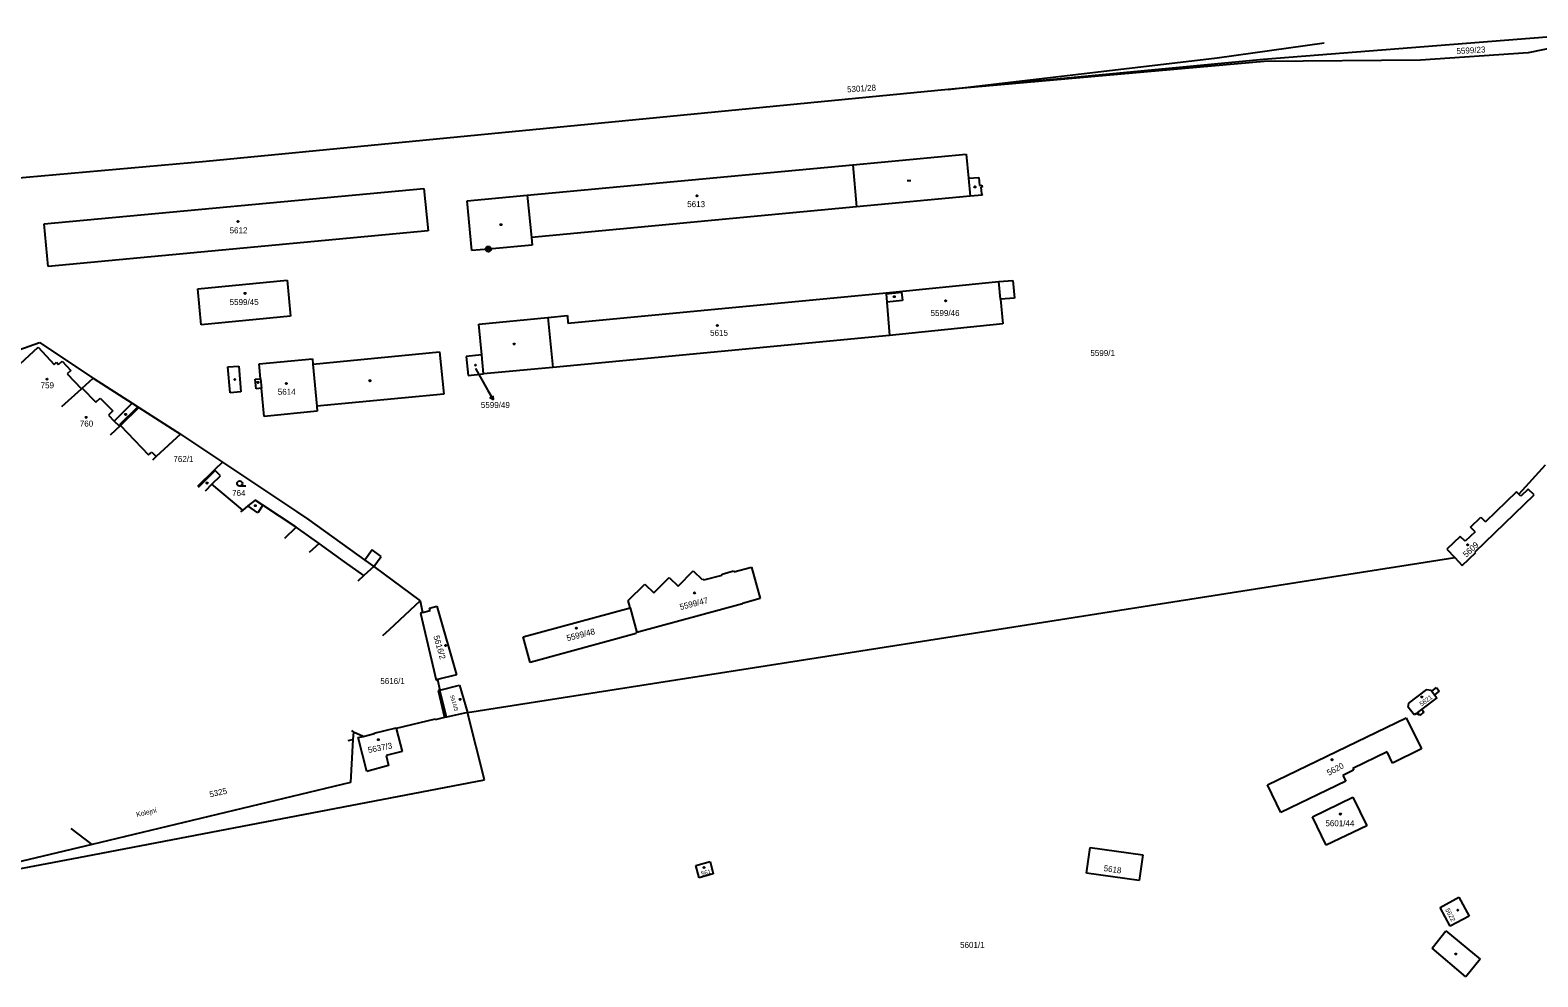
# Model space of a CAD drawing. Extents: x -825057 to -819383, y -1071633 to -1067888.
# Drawn here: x -821360.1 to -820932.9, y -1070125.7 to -1069857.7 of the extents above; entities that cross this region are included whole.
import ezdxf

# ---------------------------------------------------------------- set-up
doc = ezdxf.new("R2010")
doc.units = 0
for name, color, linetype in [('Vrstva 1', 7, 'Continuous'), ('Vrstva 15', 7, 'Continuous'), ('Vrstva 16', 7, 'Continuous'), ('Vrstva 18', 7, 'Continuous'), ('Vrstva 19', 7, 'Continuous'), ('Vrstva 24', 7, 'Continuous'), ('Vrstva 25', 7, 'Continuous'), ('Vrstva 4', 7, 'Continuous')]:
    doc.layers.add(name, color=color, linetype=linetype)

msp = doc.modelspace()

# ---------------------------------------------------------------- linework, layer by layer
at = {"layer": 'Vrstva 1'}
for p, q in [((-820904.63, -1069857.69), (-821010.61, -1069866.01)), ((-820904.63, -1069857.69), (-820935.6, -1069864.1)), ((-820935.6, -1069864.1), (-820966.1, -1069866.2)), ((-821010.61, -1069866.01), (-821099.96, -1069874.51)), ((-821010.4, -1069866.6), (-821099.96, -1069874.51)), ((-820966.1, -1069866.2), (-821010.4, -1069866.6)), ((-821099.96, -1069874.51), (-821204.97, -1069884.66)), ((-821204.97, -1069884.66), (-821310.18, -1069894.83)), ((-821310.18, -1069894.83), (-821394.16, -1069902.36)), ((-821126.99, -1069895.8), (-821094.83, -1069892.79)), ((-821094.83, -1069892.79), (-821094.2, -1069899.61)), ((-821219.2, -1069904.42), (-821126.99, -1069895.8)), ((-821356.08, -1069912.51), (-821248.48, -1069902.48)), ((-821248.48, -1069902.48), (-821247.33, -1069914.47)), ((-821094.2, -1069899.61), (-821091.31, -1069899.42)), ((-821091.31, -1069899.42), (-821091.08, -1069901.64)), ((-821091.08, -1069901.64), (-821090.41, -1069901.57)), ((-821090.35, -1069902.14), (-821090.74, -1069902.17)), ((-821090.74, -1069902.17), (-821090.55, -1069904.06)), ((-821090.41, -1069901.57), (-821090.35, -1069902.14)), ((-821236.23, -1069906.01), (-821219.2, -1069904.42)), ((-821234.89, -1069920.11), (-821236.23, -1069906.01)), ((-821093.74, -1069904.69), (-821125.89, -1069907.73)), ((-821090.36, -1069904.37), (-821093.74, -1069904.69)), ((-821090.55, -1069904.06), (-821090.4, -1069904.04)), ((-821090.4, -1069904.04), (-821090.36, -1069904.37)), ((-821125.89, -1069907.73), (-821218, -1069916.36)), ((-821354.95, -1069924.62), (-821356.08, -1069912.51)), ((-821247.33, -1069914.47), (-821354.95, -1069924.62)), ((-821230.23, -1069919.68), (-821234.89, -1069920.11)), ((-821217.78, -1069918.52), (-821230.23, -1069919.68)), ((-821218, -1069916.36), (-821217.78, -1069918.52)), ((-821312.51, -1069930.89), (-821287.26, -1069928.49)), ((-821287.26, -1069928.49), (-821286.29, -1069938.67)), ((-821117.54, -1069932.09), (-821085.6, -1069928.83)), ((-821085.6, -1069928.83), (-821081.67, -1069928.55)), ((-821081.67, -1069928.55), (-821081.2, -1069933.55)), ((-821311.6, -1069941.12), (-821312.51, -1069930.89)), ((-821207.69, -1069940.62), (-821117.54, -1069932.09)), ((-821117.54, -1069932.09), (-821117.52, -1069932.34)), ((-821117.52, -1069932.34), (-821113.16, -1069931.9)), ((-821113.16, -1069931.9), (-821112.89, -1069934.23)), ((-821112.89, -1069934.23), (-821117.33, -1069934.69)), ((-821117.33, -1069934.69), (-821116.55, -1069944.11)), ((-821081.2, -1069933.55), (-821085.16, -1069933.89)), ((-821085.16, -1069933.89), (-821084.45, -1069940.8)), ((-821286.29, -1069938.67), (-821311.6, -1069941.12)), ((-821232.95, -1069940.9), (-821213.34, -1069939.04)), ((-821232.12, -1069949.62), (-821232.95, -1069940.9)), ((-821213.34, -1069939.04), (-821207.85, -1069938.52)), ((-821207.85, -1069938.52), (-821207.69, -1069940.62)), ((-821084.45, -1069940.8), (-821116.55, -1069944.11)), ((-821116.55, -1069944.11), (-821212.01, -1069953.18)), ((-821369.19, -1069950.3), (-821357.45, -1069946.12)), ((-821357.45, -1069946.12), (-821342.21, -1069956.25)), ((-821279.92, -1069952.26), (-821244.07, -1069948.76)), ((-821244.07, -1069948.76), (-821242.89, -1069960.8)), ((-821232.12, -1069949.62), (-821236.51, -1069950.05)), ((-821236.51, -1069950.05), (-821235.98, -1069955.47)), ((-821231.61, -1069955.04), (-821232.12, -1069949.62)), ((-821295.15, -1069952.17), (-821280.05, -1069950.77)), ((-821294.76, -1069956.41), (-821295.15, -1069952.17)), ((-821280.05, -1069950.77), (-821279.92, -1069952.26)), ((-821212.01, -1069953.18), (-821231.61, -1069955.04)), ((-821345.34, -1069959.01), (-821342.21, -1069956.25)), ((-821342.21, -1069956.25), (-821331.11, -1069963.33)), ((-821296.28, -1069956.55), (-821294.76, -1069956.41)), ((-821296.04, -1069959.2), (-821296.28, -1069956.55)), ((-821235.98, -1069955.47), (-821231.61, -1069955.04)), ((-821351.12, -1069964.25), (-821345.55, -1069959.22)), ((-821345.55, -1069959.22), (-821345.34, -1069959.01)), ((-821294.51, -1069959.06), (-821296.04, -1069959.2)), ((-821293.77, -1069967.07), (-821294.51, -1069959.06)), ((-821242.89, -1069960.8), (-821278.84, -1069964.11)), ((-821329.25, -1069964.52), (-821334.5, -1069969.62)), ((-821331.11, -1069963.33), (-821329.56, -1069964.32)), ((-821329.56, -1069964.32), (-821329.25, -1069964.52)), ((-821329.25, -1069964.52), (-821317.44, -1069972.1)), ((-821278.7, -1069965.6), (-821293.77, -1069967.07)), ((-821278.84, -1069964.11), (-821278.7, -1069965.6)), ((-821334.5, -1069969.62), (-821337.41, -1069972.32)), ((-821317.44, -1069972.1), (-821324.37, -1069978.44)), ((-821317.44, -1069972.1), (-821305.58, -1069979.99)), ((-821324.37, -1069978.44), (-821325.41, -1069979.4)), ((-821305.58, -1069979.99), (-821307.81, -1069982.16)), ((-821305.58, -1069979.99), (-821296.49, -1069986.04)), ((-821307.81, -1069982.16), (-821312.67, -1069986.91)), ((-821308.56, -1069986.27), (-821306.12, -1069983.89)), ((-821307.59, -1069982.38), (-821307.81, -1069982.16)), ((-821306.12, -1069983.89), (-821307.59, -1069982.38)), ((-820930.78, -1069980.82), (-820938.28, -1069989.09)), ((-821299.82, -1069993.57), (-821308.56, -1069986.27)), ((-821296.49, -1069986.04), (-821284.57, -1069993.97)), ((-820938.97, -1069988.37), (-820947.77, -1069996.88)), ((-820938.28, -1069989.09), (-820938.97, -1069988.37)), ((-820935.6, -1069987.62), (-820937.72, -1069989.67)), ((-820933.96, -1069989.25), (-820935.6, -1069987.62)), ((-821298.38, -1069992.35), (-821299.82, -1069993.57)), ((-821296.31, -1069990.73), (-821298.38, -1069992.35)), ((-821294.15, -1069992.15), (-821296.31, -1069990.73)), ((-821284.66, -1069998.4), (-821294.15, -1069992.15)), ((-820950.64, -1070005.41), (-820933.96, -1069989.25)), ((-820937.72, -1069989.67), (-820938.28, -1069989.09)), ((-821299.82, -1069993.57), (-821300.46, -1069994.1)), ((-821284.57, -1069993.97), (-821281.1, -1069996.38)), ((-821281.1, -1069996.38), (-821265.24, -1070007.72)), ((-820951.97, -1069998.38), (-820949.05, -1069995.55)), ((-820949.05, -1069995.55), (-820947.77, -1069996.88)), ((-821278.16, -1070003.04), (-821284.66, -1069998.4)), ((-820954.86, -1070001.01), (-820958.67, -1070004.65)), ((-820953.52, -1070002.4), (-820954.86, -1070001.01)), ((-820950.68, -1069999.7), (-820953.52, -1070002.4)), ((-820950.68, -1069999.7), (-820951.97, -1069998.38)), ((-821278.16, -1070003.04), (-821280.97, -1070005.59)), ((-821271.03, -1070008.2), (-821278.16, -1070003.04)), ((-820958.67, -1070004.65), (-820956.42, -1070007.02)), ((-820954.31, -1070009.24), (-820950.48, -1070005.58)), ((-820950.48, -1070005.58), (-820950.64, -1070005.41)), ((-821265.53, -1070012.14), (-821271.03, -1070008.2)), ((-821262.68, -1070009.55), (-821265.53, -1070012.14)), ((-821265.24, -1070007.72), (-821262.68, -1070009.55)), ((-821262.68, -1070009.55), (-821249.59, -1070019.24)), ((-821160.73, -1070011.1), (-821155.64, -1070009.76)), ((-821155.64, -1070009.76), (-821153.2, -1070018.65)), ((-821087.99, -1070027.64), (-820956.42, -1070007.02)), ((-820956.42, -1070007.02), (-820954.31, -1070009.24)), ((-821265.53, -1070012.14), (-821267.22, -1070013.69)), ((-821183.33, -1070017.02), (-821179.04, -1070012.7)), ((-821179.04, -1070012.7), (-821176.47, -1070015.16)), ((-821176.47, -1070015.16), (-821172.19, -1070010.81)), ((-821172.19, -1070010.81), (-821169.68, -1070013.24)), ((-821169.68, -1070013.24), (-821169.45, -1070013.08)), ((-821169.45, -1070013.08), (-821169.15, -1070013.35)), ((-821169.15, -1070013.35), (-821163.97, -1070011.96)), ((-821164.01, -1070011.69), (-821160.8, -1070010.82)), ((-821163.97, -1070011.96), (-821164.01, -1070011.69)), ((-821160.8, -1070010.82), (-821160.73, -1070011.1)), ((-821190.61, -1070019.17), (-821185.89, -1070014.53)), ((-821185.89, -1070014.53), (-821183.33, -1070017.02)), ((-821153.2, -1070018.65), (-821158.27, -1070020.02)), ((-821249.59, -1070019.24), (-821258.36, -1070027.44)), ((-821249.59, -1070019.24), (-821248.91, -1070022.58)), ((-821248.91, -1070022.58), (-821249.48, -1070022.73)), ((-821249.48, -1070022.73), (-821245.07, -1070041.7)), ((-821248.91, -1070022.58), (-821246.7, -1070021.98)), ((-821246.88, -1070021.31), (-821244.87, -1070020.75)), ((-821246.7, -1070021.98), (-821246.88, -1070021.31)), ((-821244.87, -1070020.75), (-821244.68, -1070021.43)), ((-821244.68, -1070021.43), (-821239.23, -1070040.23)), ((-821220.34, -1070029.47), (-821190.09, -1070021.23)), ((-821190.09, -1070021.23), (-821190.61, -1070019.17)), ((-821190.09, -1070021.23), (-821188.13, -1070028.23)), ((-821158.23, -1070020.16), (-821188.13, -1070028.23)), ((-821158.27, -1070020.02), (-821158.23, -1070020.16)), ((-821258.36, -1070027.44), (-821260.23, -1070029.19)), ((-821236.18, -1070050.87), (-821087.99, -1070027.64)), ((-821218.37, -1070036.69), (-821220.34, -1070029.47)), ((-821188.38, -1070028.53), (-821218.37, -1070036.69)), ((-821188.13, -1070028.23), (-821188.44, -1070028.31)), ((-821188.44, -1070028.31), (-821188.38, -1070028.53)), ((-821245.07, -1070041.7), (-821244.63, -1070041.59)), ((-821239.23, -1070040.23), (-821244.63, -1070041.59)), ((-821244.63, -1070041.59), (-821243.95, -1070044.52)), ((-821243.95, -1070044.52), (-821238.41, -1070043.13)), ((-821238.41, -1070043.13), (-821236.18, -1070050.87)), ((-820962.96, -1070044.81), (-820961.6, -1070043.79)), ((-820961.6, -1070043.79), (-820960.88, -1070044.8)), ((-821243.95, -1070044.52), (-821244.41, -1070044.64)), ((-821244.41, -1070044.64), (-821242.69, -1070052.35)), ((-820969.67, -1070049.36), (-820969.48, -1070048.21)), ((-820969.48, -1070048.21), (-820964.32, -1070044.38)), ((-820961.5, -1070046.76), (-820965.8, -1070049.99)), ((-820964.32, -1070044.38), (-820963.14, -1070044.56)), ((-820963.14, -1070044.56), (-820962.96, -1070044.81)), ((-820960.88, -1070044.8), (-820962.17, -1070045.86)), ((-820962.17, -1070045.86), (-820961.5, -1070046.76)), ((-821245.31, -1070052.82), (-821256.32, -1070055.41)), ((-821245.27, -1070052.96), (-821245.31, -1070052.82)), ((-821242.69, -1070052.35), (-821245.27, -1070052.96)), ((-821242.12, -1070052.22), (-821242.69, -1070052.35)), ((-821236.18, -1070050.87), (-821242.12, -1070052.22)), ((-821231.29, -1070069.95), (-821236.18, -1070050.87)), ((-821009.46, -1070071.37), (-820970.17, -1070052.4)), ((-820970.17, -1070052.4), (-820965.84, -1070061.19)), ((-820967.91, -1070051.58), (-820969.67, -1070049.36)), ((-820967.44, -1070051.23), (-820967.91, -1070051.58)), ((-820967.25, -1070051.47), (-820967.44, -1070051.23)), ((-820966.84, -1070051.16), (-820967.25, -1070051.47)), ((-820966.42, -1070051.71), (-820966.84, -1070051.16)), ((-820965.18, -1070050.82), (-820966.42, -1070051.71)), ((-820965.8, -1070049.99), (-820965.18, -1070050.82)), ((-821269, -1070055.95), (-821268.48, -1070056.5)), ((-821268.48, -1070056.5), (-821268.6, -1070058.51)), ((-821265.69, -1070057.64), (-821268.48, -1070056.5)), ((-821265.69, -1070057.64), (-821262.54, -1070056.84)), ((-821262.57, -1070056.72), (-821256.38, -1070055.19)), ((-821262.54, -1070056.84), (-821262.57, -1070056.72)), ((-821256.38, -1070055.19), (-821256.32, -1070055.41)), ((-821256.32, -1070055.41), (-821254.68, -1070061.91)), ((-821269.94, -1070058.82), (-821268.6, -1070058.51)), ((-821268.6, -1070058.51), (-821269.3, -1070070.69)), ((-821267.13, -1070058), (-821265.69, -1070057.64)), ((-821264.67, -1070067.57), (-821267.13, -1070058)), ((-820965.84, -1070061.19), (-820974.11, -1070065.2)), ((-821254.68, -1070061.91), (-821259.17, -1070063.06)), ((-821259.17, -1070063.06), (-821258.49, -1070065.94)), ((-820975.63, -1070062.06), (-820985.32, -1070066.76)), ((-820974.11, -1070065.2), (-820975.63, -1070062.06)), ((-821344.25, -1070091.52), (-821231.29, -1070069.95)), ((-821258.49, -1070065.94), (-821264.67, -1070067.57)), ((-820985.1, -1070067.21), (-820988.11, -1070068.69)), ((-820988.11, -1070068.69), (-820987.3, -1070070.36)), ((-820985.32, -1070066.76), (-820985.1, -1070067.21)), ((-821269.3, -1070070.69), (-821342.51, -1070088.26)), ((-821005.67, -1070079.24), (-821009.46, -1070071.37)), ((-820987.3, -1070070.36), (-821005.67, -1070079.24)), ((-820996.77, -1070080.39), (-820985.3, -1070074.82)), ((-820985.3, -1070074.82), (-820981.37, -1070082.94)), ((-820992.84, -1070088.49), (-820996.77, -1070080.39)), ((-821342.51, -1070088.26), (-821348.44, -1070083.73)), ((-820981.37, -1070082.94), (-820992.84, -1070088.49)), ((-821342.51, -1070088.26), (-821364.34, -1070093.49)), ((-821060.77, -1070096.38), (-821059.71, -1070089.09)), ((-821059.71, -1070089.09), (-821044.85, -1070091.16)), ((-821044.85, -1070091.16), (-821045.87, -1070098.45)), ((-821444.24, -1070110.62), (-821344.25, -1070091.52)), ((-821171.43, -1070094.17), (-821167.43, -1070093.11)), ((-821170.51, -1070097.67), (-821171.43, -1070094.17)), ((-821167.43, -1070093.11), (-821166.5, -1070096.61)), ((-821166.5, -1070096.61), (-821170.51, -1070097.67)), ((-821045.87, -1070098.45), (-821060.77, -1070096.38)), ((-820960.53, -1070106.07), (-820955.3, -1070103.16)), ((-820955.3, -1070103.16), (-820952.4, -1070108.52)), ((-820957.7, -1070111.36), (-820960.53, -1070106.07)), ((-820952.4, -1070108.52), (-820957.7, -1070111.36))]:
    msp.add_line(p, q, dxfattribs=at)
at = {"layer": 'Vrstva 16'}
for p, q in [((-821233.88, -1069953.53), (-821230.37, -1069959.7)), ((-821230.37, -1069959.7), (-821228.885, -1069962.307))]:
    msp.add_line(p, q, dxfattribs=at)
msp.add_lwpolyline([(-821228.946, -1069961.19), (-821228.885, -1069962.307), (-821229.815, -1069961.685)], dxfattribs=at)
at = {"layer": 'Vrstva 24'}
for p, q in [((-821230.98, -1069919.68), (-821229.48, -1069919.68)), ((-821230.954, -1069919.486), (-821229.506, -1069919.874)), ((-821230.954, -1069919.874), (-821229.506, -1069919.486)), ((-821230.879, -1069919.305), (-821229.581, -1069920.055)), ((-821230.879, -1069920.055), (-821229.581, -1069919.305)), ((-821230.76, -1069920.21), (-821229.7, -1069919.15)), ((-821230.76, -1069919.15), (-821229.7, -1069920.21))]:
    msp.add_line(p, q, dxfattribs=at)
msp.add_circle((-821230.23, -1069919.68), 0.75, dxfattribs=at)
at = {"layer": 'Vrstva 25'}
for p, q in [((-821111.56, -1069900.29), (-821110.56, -1069900.29)), ((-821298.94, -1069986.81), (-821300.69, -1069986.81))]:
    msp.add_line(p, q, dxfattribs=at)
for centre, radius in [((-821092.38, -1069902.08), 0.175), ((-821171.13, -1069904.59), 0.175), ((-821301.17, -1069911.86), 0.175), ((-821226.67, -1069912.77), 0.175), ((-821299.17, -1069932.23), 0.175), ((-821115.23, -1069933.14), 0.175), ((-821100.7, -1069934.33), 0.175), ((-821165.39, -1069941.31), 0.175), ((-821222.93, -1069946.55), 0.175), ((-821233.88, -1069952.55), 0.175), ((-821355.26, -1069956.49), 0.175), ((-821302.08, -1069956.59), 0.175), ((-821295.53, -1069957.43), 0.175), ((-821287.48, -1069957.72), 0.175), ((-821263.79, -1069956.95), 0.175), ((-821344.17, -1069967.33), 0.175), ((-821333.02, -1069966.49), 0.175), ((-821309.93, -1069985.93), 0.175), ((-821300.69, -1069986.06), 0.75), ((-821296.25, -1069992.31), 0.175), ((-820952.8, -1070003.43), 0.175), ((-821171.83, -1070017.03), 0.175), ((-821205.33, -1070027.01), 0.175), ((-821242.35, -1070031.91), 0.175), ((-821238.22, -1070047.18), 0.175), ((-820965.78, -1070046.51), 0.175), ((-821261.4, -1070058.57), 0.175), ((-820991.21, -1070064.27), 0.175), ((-820988.84, -1070079.65), 0.175), ((-821169.14, -1070094.76), 0.175), ((-820955.56, -1070106.85), 0.175), ((-820956.12, -1070119.28), 0.175)]:
    msp.add_circle(centre, radius, dxfattribs=at)
at = {"layer": 'Vrstva 4'}
for p, q in [((-821023.78, -1069865.56), (-820993.46, -1069861.27)), ((-821058.25, -1069869.59), (-821023.78, -1069865.56)), ((-821099.96, -1069874.51), (-821058.25, -1069869.59)), ((-821126.99, -1069895.8), (-821125.89, -1069907.73)), ((-821094.2, -1069899.61), (-821093.74, -1069904.69)), ((-821219.2, -1069904.42), (-821218, -1069916.36)), ((-821085.16, -1069933.89), (-821085.6, -1069928.83)), ((-821117.52, -1069932.34), (-821117.33, -1069934.69)), ((-821213.34, -1069939.04), (-821212.01, -1069953.18)), ((-821365.33, -1069954.47), (-821357.83, -1069947.42)), ((-821357.83, -1069947.42), (-821353.22, -1069952.34)), ((-821353.22, -1069952.34), (-821352.55, -1069951.72)), ((-821352.55, -1069951.72), (-821351.98, -1069952.32)), ((-821351.98, -1069952.32), (-821350.99, -1069951.39)), ((-821350.99, -1069951.39), (-821348.54, -1069954.01)), ((-821348.54, -1069954.01), (-821349.56, -1069954.99)), ((-821304.03, -1069953.05), (-821300.95, -1069952.82)), ((-821303.42, -1069960.39), (-821304.03, -1069953.05)), ((-821300.95, -1069952.82), (-821300.38, -1069960.11)), ((-821279.92, -1069952.26), (-821278.84, -1069964.11)), ((-821349.56, -1069954.99), (-821345.55, -1069959.22)), ((-821294.76, -1069956.41), (-821294.51, -1069959.06)), ((-821345.34, -1069959.01), (-821341.47, -1069963.03)), ((-821341.47, -1069963.03), (-821340.25, -1069961.85)), ((-821340.25, -1069961.85), (-821338.04, -1069964.09)), ((-821300.38, -1069960.11), (-821303.42, -1069960.39)), ((-821338.04, -1069964.09), (-821336.65, -1069965.46)), ((-821336.65, -1069965.46), (-821337.85, -1069966.71)), ((-821337.85, -1069966.71), (-821336.21, -1069968.38)), ((-821336.21, -1069968.38), (-821331.11, -1069963.33)), ((-821329.56, -1069964.32), (-821334.71, -1069969.41)), ((-821336.21, -1069968.38), (-821334.96, -1069969.65)), ((-821334.96, -1069969.65), (-821334.71, -1069969.41)), ((-821334.71, -1069969.41), (-821334.5, -1069969.62)), ((-821334.5, -1069969.62), (-821326.56, -1069977.97)), ((-821326.56, -1069977.97), (-821325.57, -1069977.17)), ((-821325.57, -1069977.17), (-821324.37, -1069978.44)), ((-821312.33, -1069987.11), (-821307.59, -1069982.38)), ((-821308.56, -1069986.27), (-821310.51, -1069988.18)), ((-821295.54, -1069994.37), (-821298.38, -1069992.35)), ((-821294.15, -1069992.15), (-821295.54, -1069994.37)), ((-821287.93, -1070001.49), (-821284.66, -1069998.4)), ((-821263.13, -1070004.85), (-821265.24, -1070007.72)), ((-821260.59, -1070006.68), (-821263.13, -1070004.85)), ((-821262.68, -1070009.55), (-821260.59, -1070006.68)), ((-821242.12, -1070052.22), (-821243.95, -1070044.52)), ((-820962.96, -1070044.81), (-820962.17, -1070045.86)), ((-820967.02, -1070050.91), (-820967.44, -1070051.23)), ((-820965.8, -1070049.99), (-820967.02, -1070050.91)), ((-820962.88, -1070117.59), (-820958.97, -1070112.75)), ((-820958.97, -1070112.75), (-820949.27, -1070120.76)), ((-820953.32, -1070125.73), (-820962.88, -1070117.59)), ((-820949.27, -1070120.76), (-820953.32, -1070125.73))]:
    msp.add_line(p, q, dxfattribs=at)

# ---------------------------------------------------------------- texts
at = {"layer": 'Vrstva 15'}
msp.add_text('Kolejní', height=1.4, rotation=12.6, dxfattribs=at).set_placement((-821329.83, -1070080.481))
at = {"layer": 'Vrstva 16'}
for s, p in [('5599/49', (-821232.358, -1069964.66)), ('5601/1', (-821096.588, -1070117.54))]:
    msp.add_text(s, height=1.7, dxfattribs=at).set_placement(p)
at = {"layer": 'Vrstva 18'}
for s, rotation, p in [('5599/23', 3.6, (-820955.891, -1069864.491)), ('5301/28', 3.6, (-821128.565, -1069875.301)), ('5325', 12.6, (-821309.055, -1070074.948)), ('5618', 351.9, (-821056.003, -1070095.776))]:
    msp.add_text(s, height=1.7, rotation=rotation, dxfattribs=at).set_placement(p)
for s, p in [('5599/1', (-821059.663, -1069949.95)), ('764', (-821302.838, -1069989.58)), ('5616/1', (-821260.844, -1070042.83))]:
    msp.add_text(s, height=1.7, dxfattribs=at).set_placement(p)
at = {"layer": 'Vrstva 19'}
for s, height, p in [('5613', 1.7, (-821173.894, -1069907.8)), ('5612', 1.7, (-821303.552, -1069915.22)), ('5599/45', 1.7, (-821303.54, -1069935.52)), ('5599/46', 1.7, (-821104.958, -1069938.63)), ('5615', 1.7, (-821167.418, -1069944.24)), ('5599/49', 0.1, (-821234.082, -1069953.53)), ('759', 1.7, (-821357.09, -1069959.09)), ('5614', 1.7, (-821289.886, -1069960.94)), ('760', 1.7, (-821345.982, -1069969.93)), ('762/1', 1.7, (-821319.462, -1069979.95)), ('5601/44', 1.7, (-820993.08, -1070083.09))]:
    msp.add_text(s, height=height, dxfattribs=at).set_placement(p)
for s, height, rotation, p in [('5609', 1.7, 43.2, (-820953.17, -1070007.09)), ('5599/47', 1.7, 14.2065, (-821175.801, -1070021.893)), ('5599/48', 1.7, 14.2425, (-821207.842, -1070030.699)), ('5616/2', 1.7, 286.0929, (-821245.832, -1070029.329)), ('5616/3', 1.1, 286.3665, (-821241.099, -1070046.152)), ('5621', 1.3, 36.9, (-820965.823, -1070049.216)), ('5637/3', 1.7, 11.1447, (-821264.174, -1070062.384)), ('5620', 1.7, 27.9, (-820992.13, -1070068.85)), ('5617', 1.2, 13.5, (-821169.78, -1070097.11)), ('5622', 1.3, 297.9, (-820959.17, -1070106.719))]:
    msp.add_text(s, height=height, rotation=rotation, dxfattribs=at).set_placement(p)

doc.saveas('drawing.dxf')
